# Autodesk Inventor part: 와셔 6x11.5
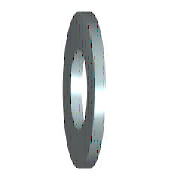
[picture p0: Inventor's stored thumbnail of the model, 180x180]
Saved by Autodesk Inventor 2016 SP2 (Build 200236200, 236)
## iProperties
IsCustomPart: 1
Created: 2012-02
Part Number: 와셔 6x11.5
Material: 강철, 연강
Description: 평면 와셔
Document SubType Name: Modeling
Standard: KS B 1326
Designer: mduedu
Standards Organization: KS
Language: ko-KR
Size Designation: 6x11.5
Categories: <MemberInstance><Categories><Category DisplayName="조임쇠" InternalName="e4da775c-781d-43d5-af7c-5136215cf5a6" Mnemonic="FSTN"><Category DisplayName="와셔" InternalN
Density: 1 g/cm^3
Appearance: 주황색
Author: mduedu
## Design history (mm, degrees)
sketch "스케치"
  geometry: C1 r 5.75 at (0, 0); C2 r 3.2 at (0, 0); 1 further point
  constraints: 2 centre point, 2 coincident
  dimensions: "d0" = 6.4 diameter of C2 (= SD1); "d1" = 11.5 diameter of C1 (= SD2)
extrude "본체" new body sketch "스케치" distance "d2" = 1.6 (= SD); taper "d3" = 0 deg
workaxis "Work Axis1"
workplane "Work Plane1"
body "Solid1"
other parameters: "SD1" = 6.4 [user parameter; used in 1 equation term], "SD2" = 11.5 [user parameter; used in 1 equation term], "SD" = 1.6 [user parameter; used in 1 equation term], "d4" = 0, "d5" = 0, "d6" = 0, "d7" = 0, "NND" = 6 [user parameter]
